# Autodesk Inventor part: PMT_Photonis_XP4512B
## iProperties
Shininess: 64.0
Length Units: 11269
Angle Units: 11279
Time Units: 11290
Mass Units: 11283
Length Display Precision: 3
Angle Display Precision: 2
Compacted: True
Part Number: PMT_Photonis_XP4512B
Document SubType Name: Modeling
Created: 2005-04
Material: Clear Fused Quartz
Designer: John Blackburn
Manufacturer: Standard
Standards Organization: Custom
Density: 0.0
Volumn: 0.0
Area: 0.0
PropertySet Name: Model Information
Control State: 0
Master: False
Checked Out: False
Author: John Blackburn
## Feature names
1. Extrusion1
2. Revolution1
3. Extrusion2
4. Extrusion3
5. Extrusion4
6. Extrusion5
7. Chamfer1
8. Revolution2
9. Extrusion6
10. Fillet1
11. Circular Pattern1
12. Fillet2
